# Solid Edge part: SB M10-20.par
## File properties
Author: Dan
Template: metric part.par
Last saved by: Dan
Revision: 5
Application: Solid Edge
Material: Steel
Face Style: Steel
Fill Style: ANSI32(Steel)
Virtual Style: Machined steel
Coef. of Thermal Exp: 1.3e-05
Thermal Conductivity: 32.0
Specific Heat: 481.0
Modulus of Elasticity: 199947953000.0
Poisson's Ratio: 0.29
Yield Stress: 262000766.0
Ultimate Stress: 358527364.0
Elongation: 0.0
Density: 7833.000 kg/m^3
Accuracy: 0.990
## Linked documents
SBM10-20.par
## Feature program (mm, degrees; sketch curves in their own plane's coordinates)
part copy "CopiedPart_1"
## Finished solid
Body 1: solid body, 16 faces, 26 edges, 12 vertices.
  Faces by surface: plane 11, cylinder 3, cone 1, torus 1
  Edges by curve: line 18, circle 8
Bounding box of the edges (mm; curved faces can reach further): 43.000 x 18.000 x 18.000, from (-29, -9, -9) to (14, 9, 9).
Cylindrical faces by radius (mm): R5 x1, R6 x1, R9 x1
Conical faces (half-angle, radius in mm at the cone's reference point): 45 deg R5 x1
Toroidal faces (ring radius, tube radius in mm): R8 r1 x1
Planar faces by outward normal: +x 3, +z 1, -x 2, -z 1, oblique 4
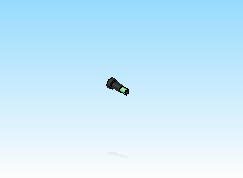
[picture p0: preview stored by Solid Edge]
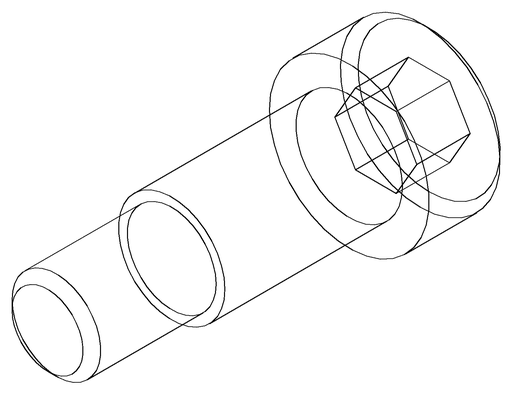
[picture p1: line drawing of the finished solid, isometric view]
